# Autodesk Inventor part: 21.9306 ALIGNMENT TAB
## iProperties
Created: 2012-07
Part Number: 21.9306 ALIGNMENT TAB
Document SubType Name: Modeling
Designer: Administrator
Density: 1.13 g/cm^3
Material: Nylon Composite (Nylon, molybdenum disulphide)
Mass: 1.03236 g
Surface Area: 12.1941 cm^2
Volume: 0.913593 cm^3
Author: Administrator
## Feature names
1. Base1
